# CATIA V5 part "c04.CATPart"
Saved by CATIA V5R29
Part number: c04
Bounding box of the stored display mesh (mm): x -18 to 0, y -67.553 to 154.447, z -187.568 to -87.568
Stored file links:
  C:\Users\제5강의실-23\Desktop\c04.CATPart
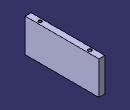
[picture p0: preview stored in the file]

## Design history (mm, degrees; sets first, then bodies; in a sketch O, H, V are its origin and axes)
Body1 (main body)
  Sketch1 on yz-plane, origin (0, 0, 0), H (0, 1, 0), V (0, 0, 1)
    line L1 (154.4473, -87.5676) -> (-67.5527, -87.5676)
    line L2 (-67.5527, -87.5676) -> (-67.5527, -187.5676)
    line L3 (-67.5527, -187.5676) -> (154.4473, -187.5676)
    line L4 (154.4473, -187.5676) -> (154.4473, -87.5676)
    length L3 = 222
    length L2 = 100
    horizontal: L1 H, L3 H
    vertical: L2 V, L4 V
  Pad1: profile Sketch1, direction (-1, 0, 0), length 18
  Sketch2 on face of Pad1 from Sketch1.L1, origin (0, 0, -87.5676), H (1, 0, 0), V (0, 1, 0)
    circle A1 centre (-9, 118.4473) radius 4.15
    point P1 (-9, 118.4473)
    circle A2 centre (-9, -31.5527) radius 4.15
    point P2 (-9, -31.5527)
    reference intersected line E1 (0, 154.4473) -> (0, -67.5527) from start face of Pad1
    reference intersected line E2 (0, -67.5527) -> (-18, -67.5527) from face of Pad1 from Sketch1.L2
    reference intersected line E3 (-18, 154.4473) -> (0, 154.4473) from face of Pad1 from Sketch1.L4
    reference intersected line E4 (0, 154.4473) -> (0, -67.5527) from start face of Pad1
    radius A1 = 4.15
    radius A2 = 4.15
    distance P2 E1 = 9
    distance P1 P2 = 150
    distance P2 E2 = 36
    distance P1 E3 = 36 (reference)
    distance P1 E4 = 9
  Pocket1: profile Sketch2, direction (0, 0, -1), length 60
  Chamfer1: length 1, angle 45, on face of Pocket1 from Sketch2.A1; face of Pocket1 from Sketch2.A2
